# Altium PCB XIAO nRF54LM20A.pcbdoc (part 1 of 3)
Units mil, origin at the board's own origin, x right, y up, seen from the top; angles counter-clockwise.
Board outline 1393.7 x 1456.69 mil, 6 copper layers (Top Layer, L2.Cu, L3.Cu, L4.Cu, L5.Cu, Bottom Layer), stack 1.58 mil thick; 146 components, 0 nets, 519 pads, 402 vias.
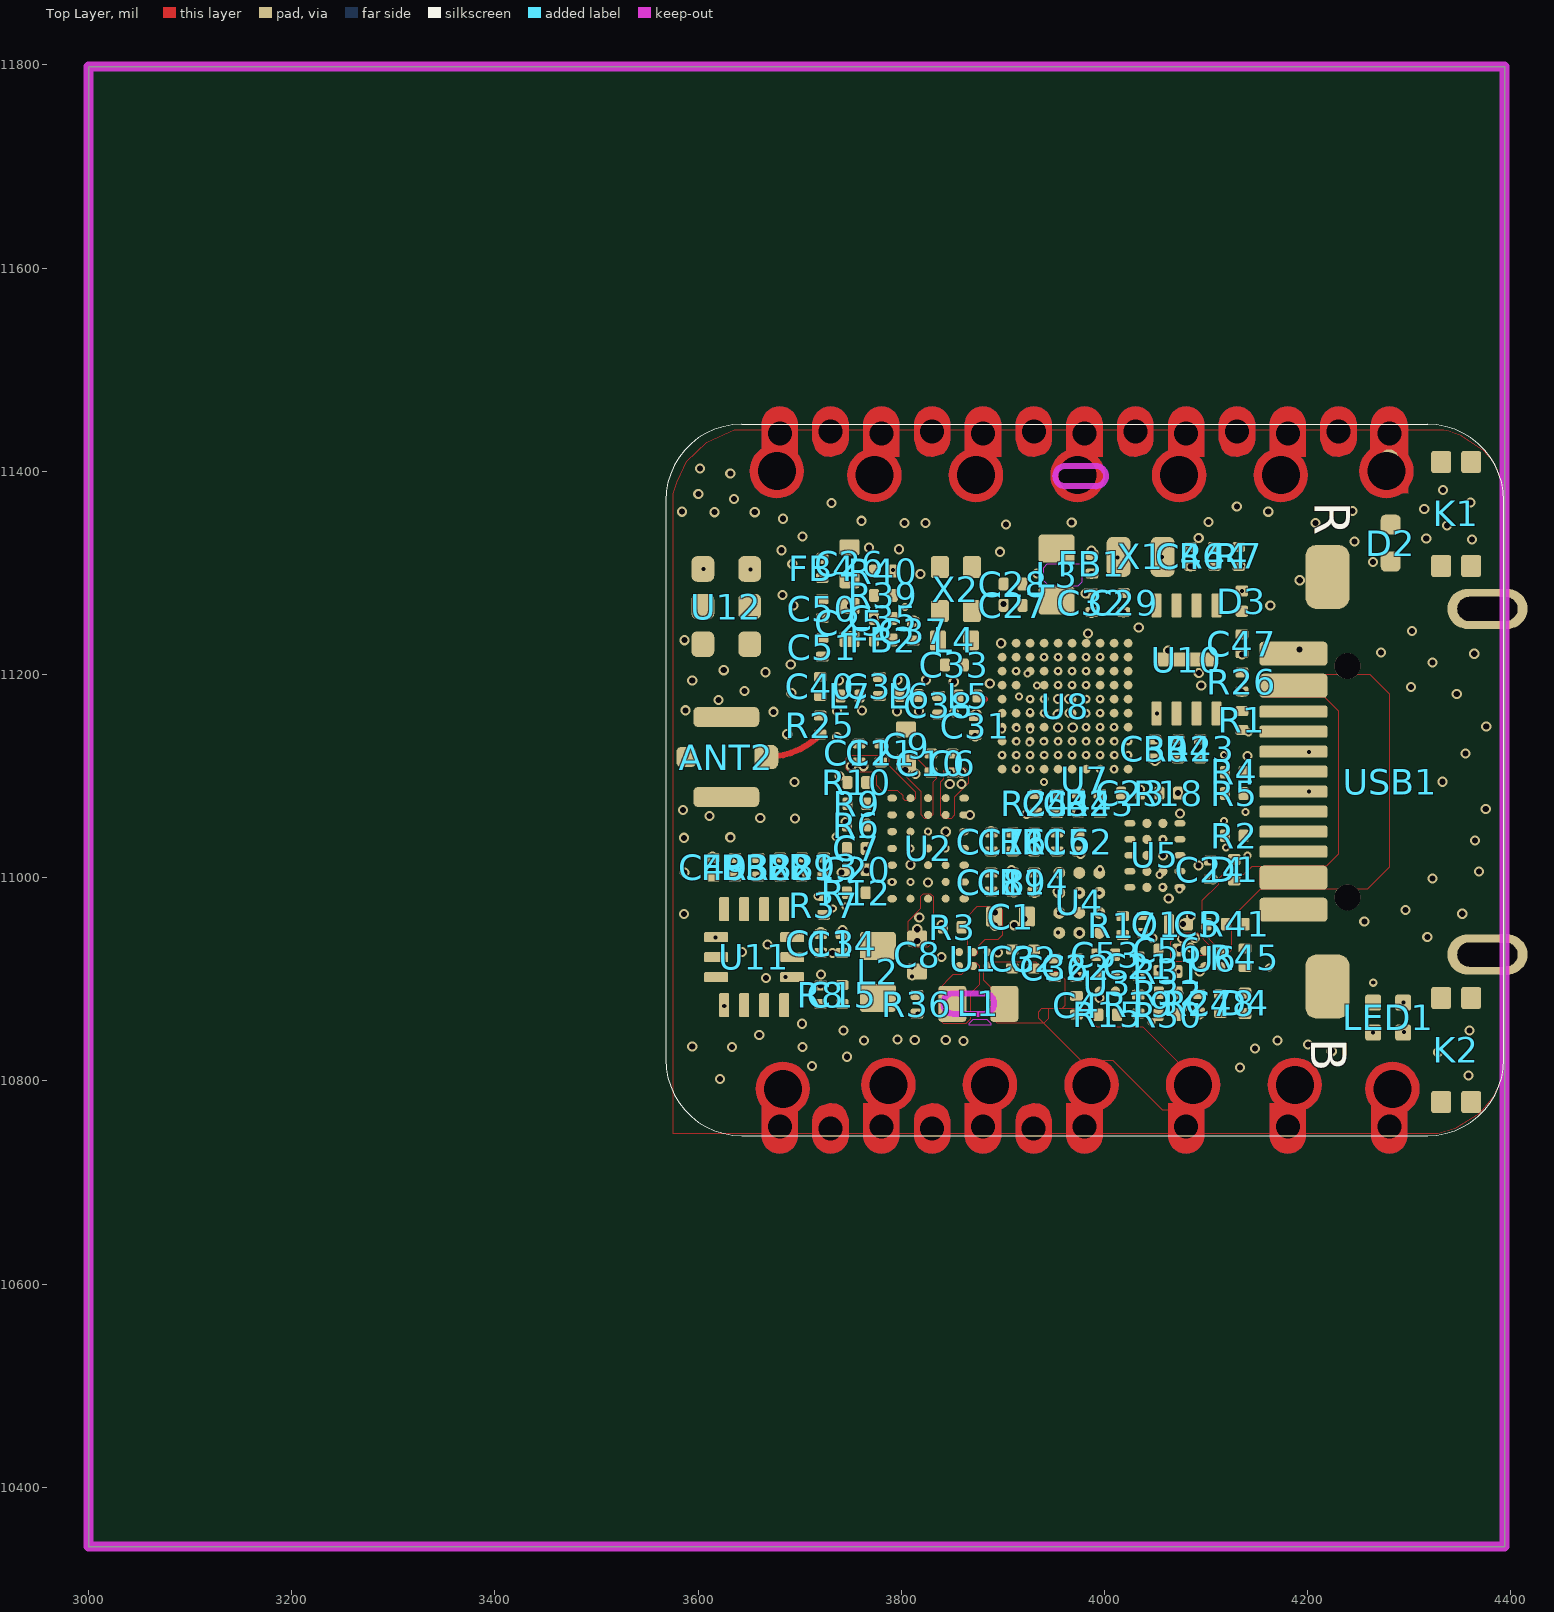
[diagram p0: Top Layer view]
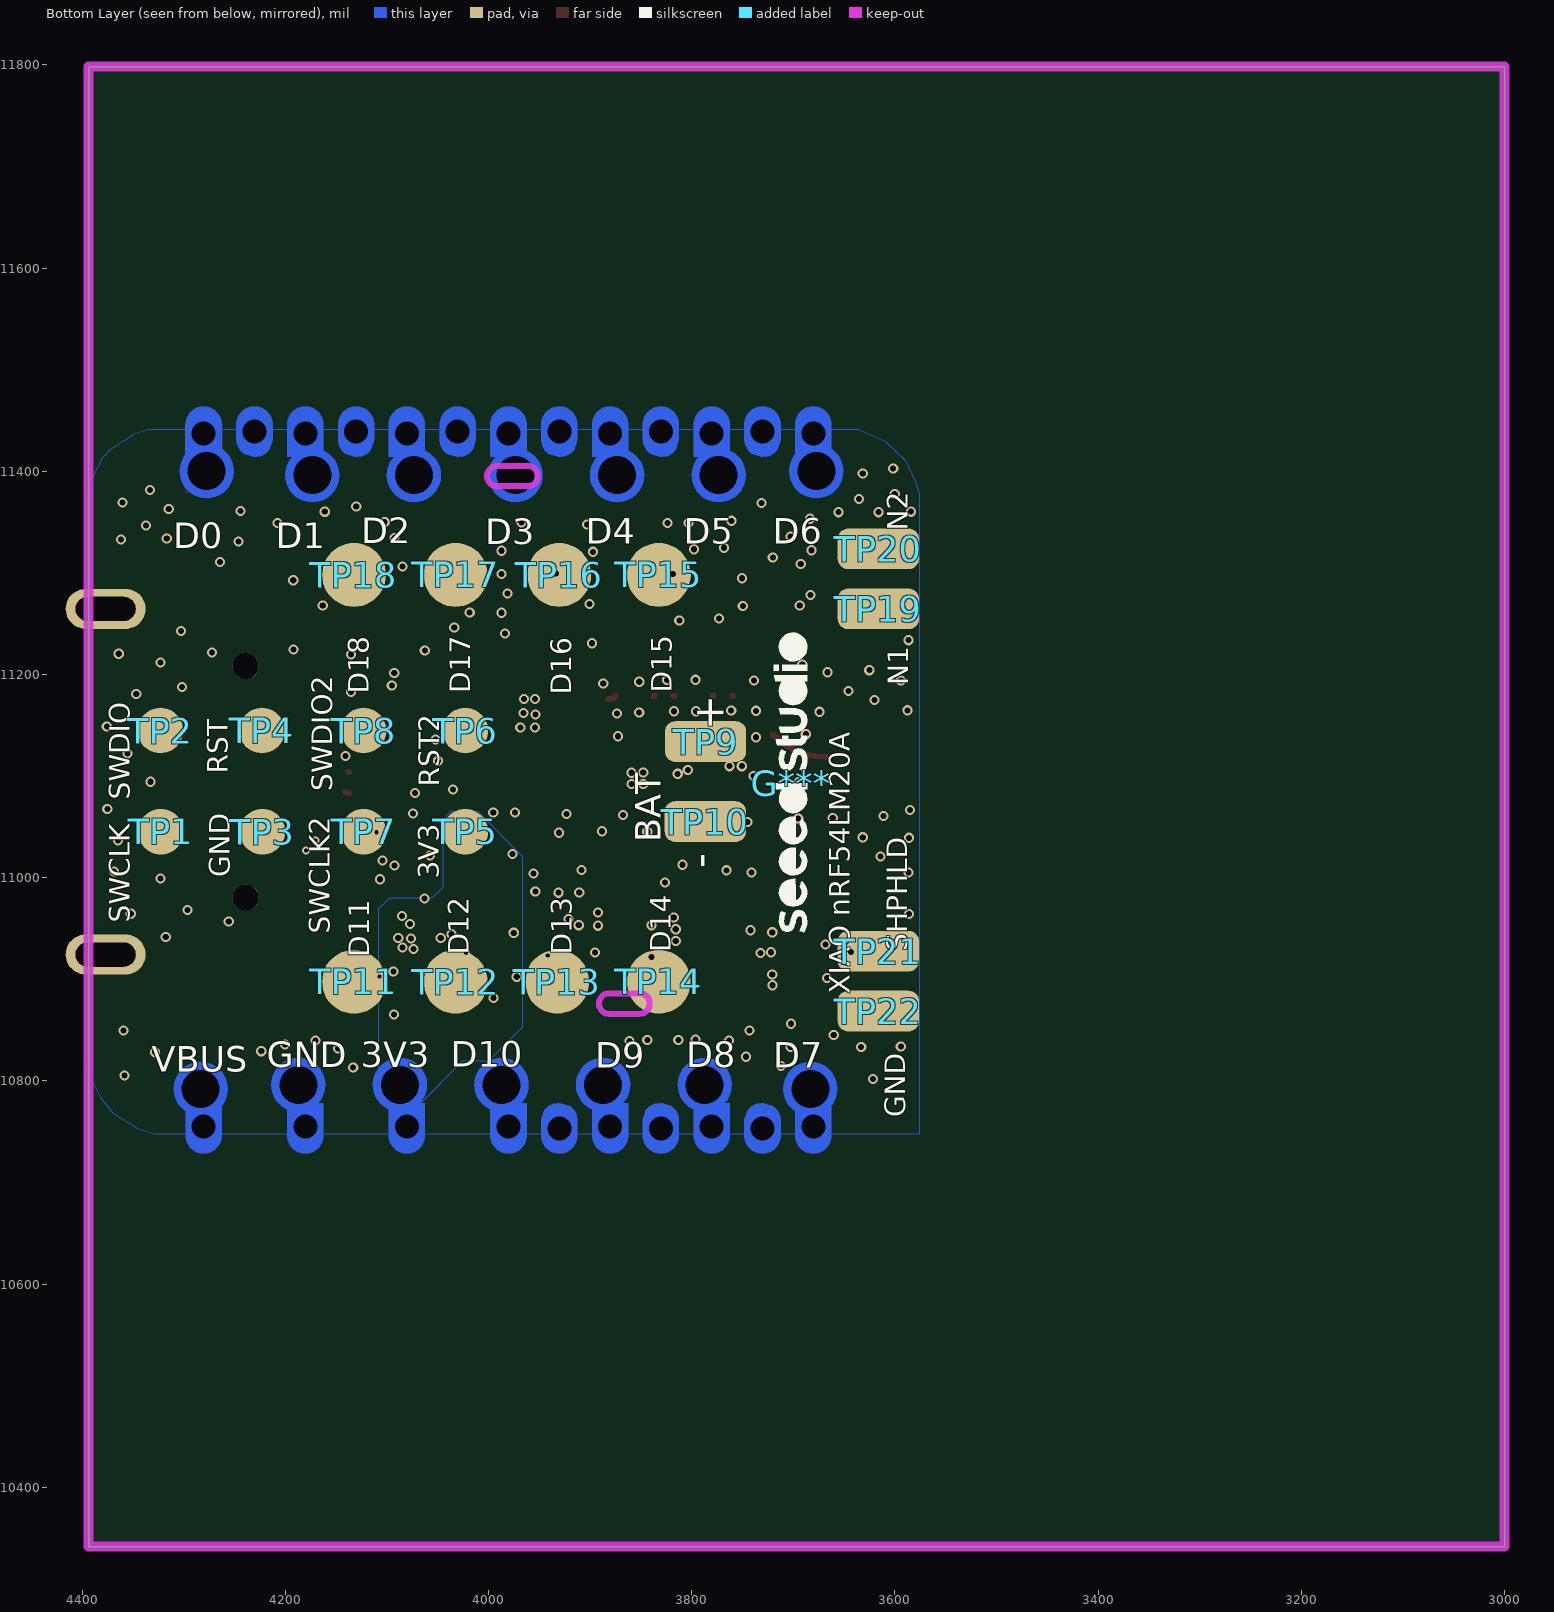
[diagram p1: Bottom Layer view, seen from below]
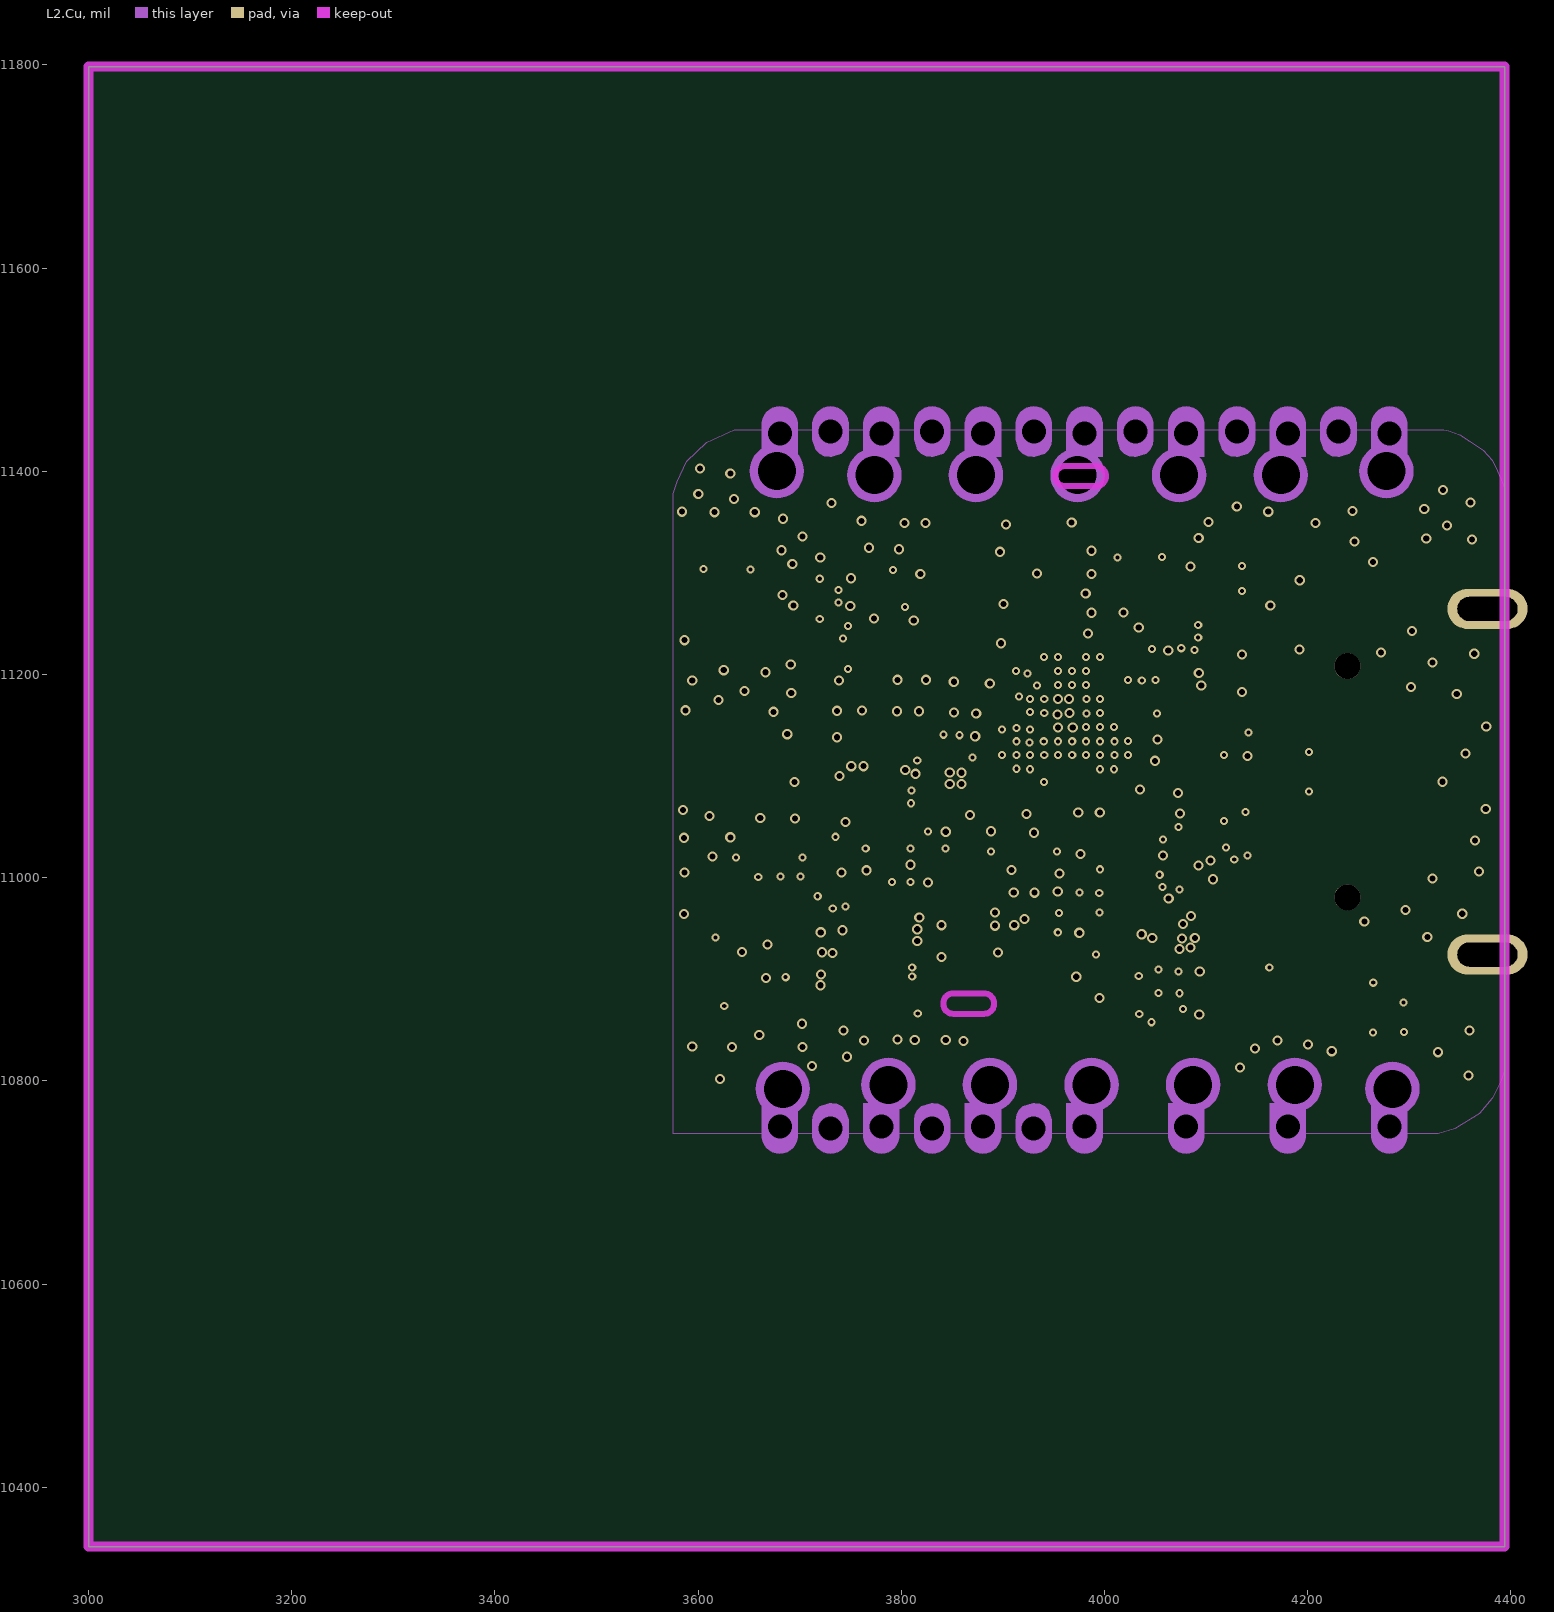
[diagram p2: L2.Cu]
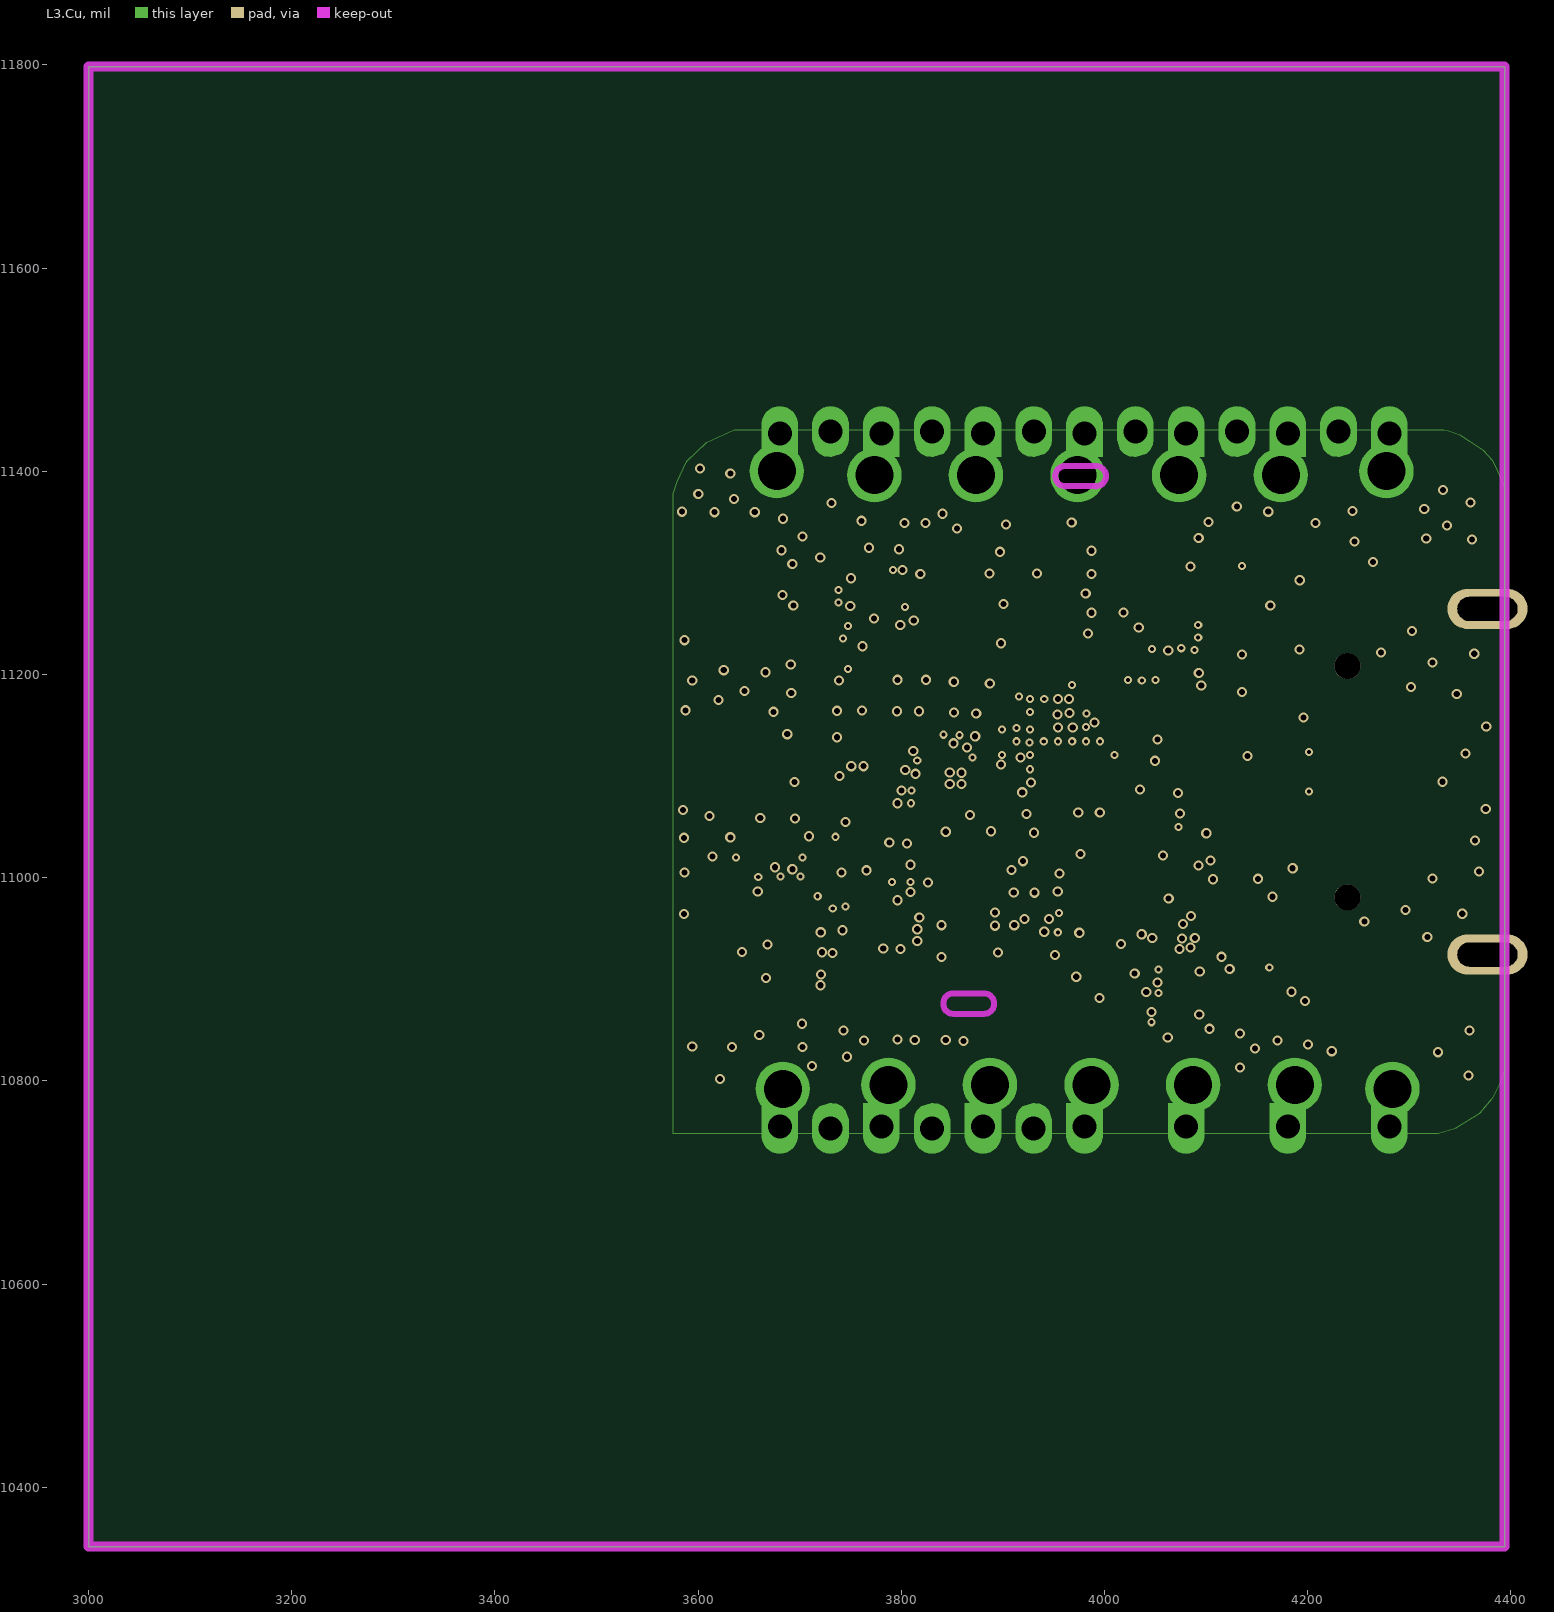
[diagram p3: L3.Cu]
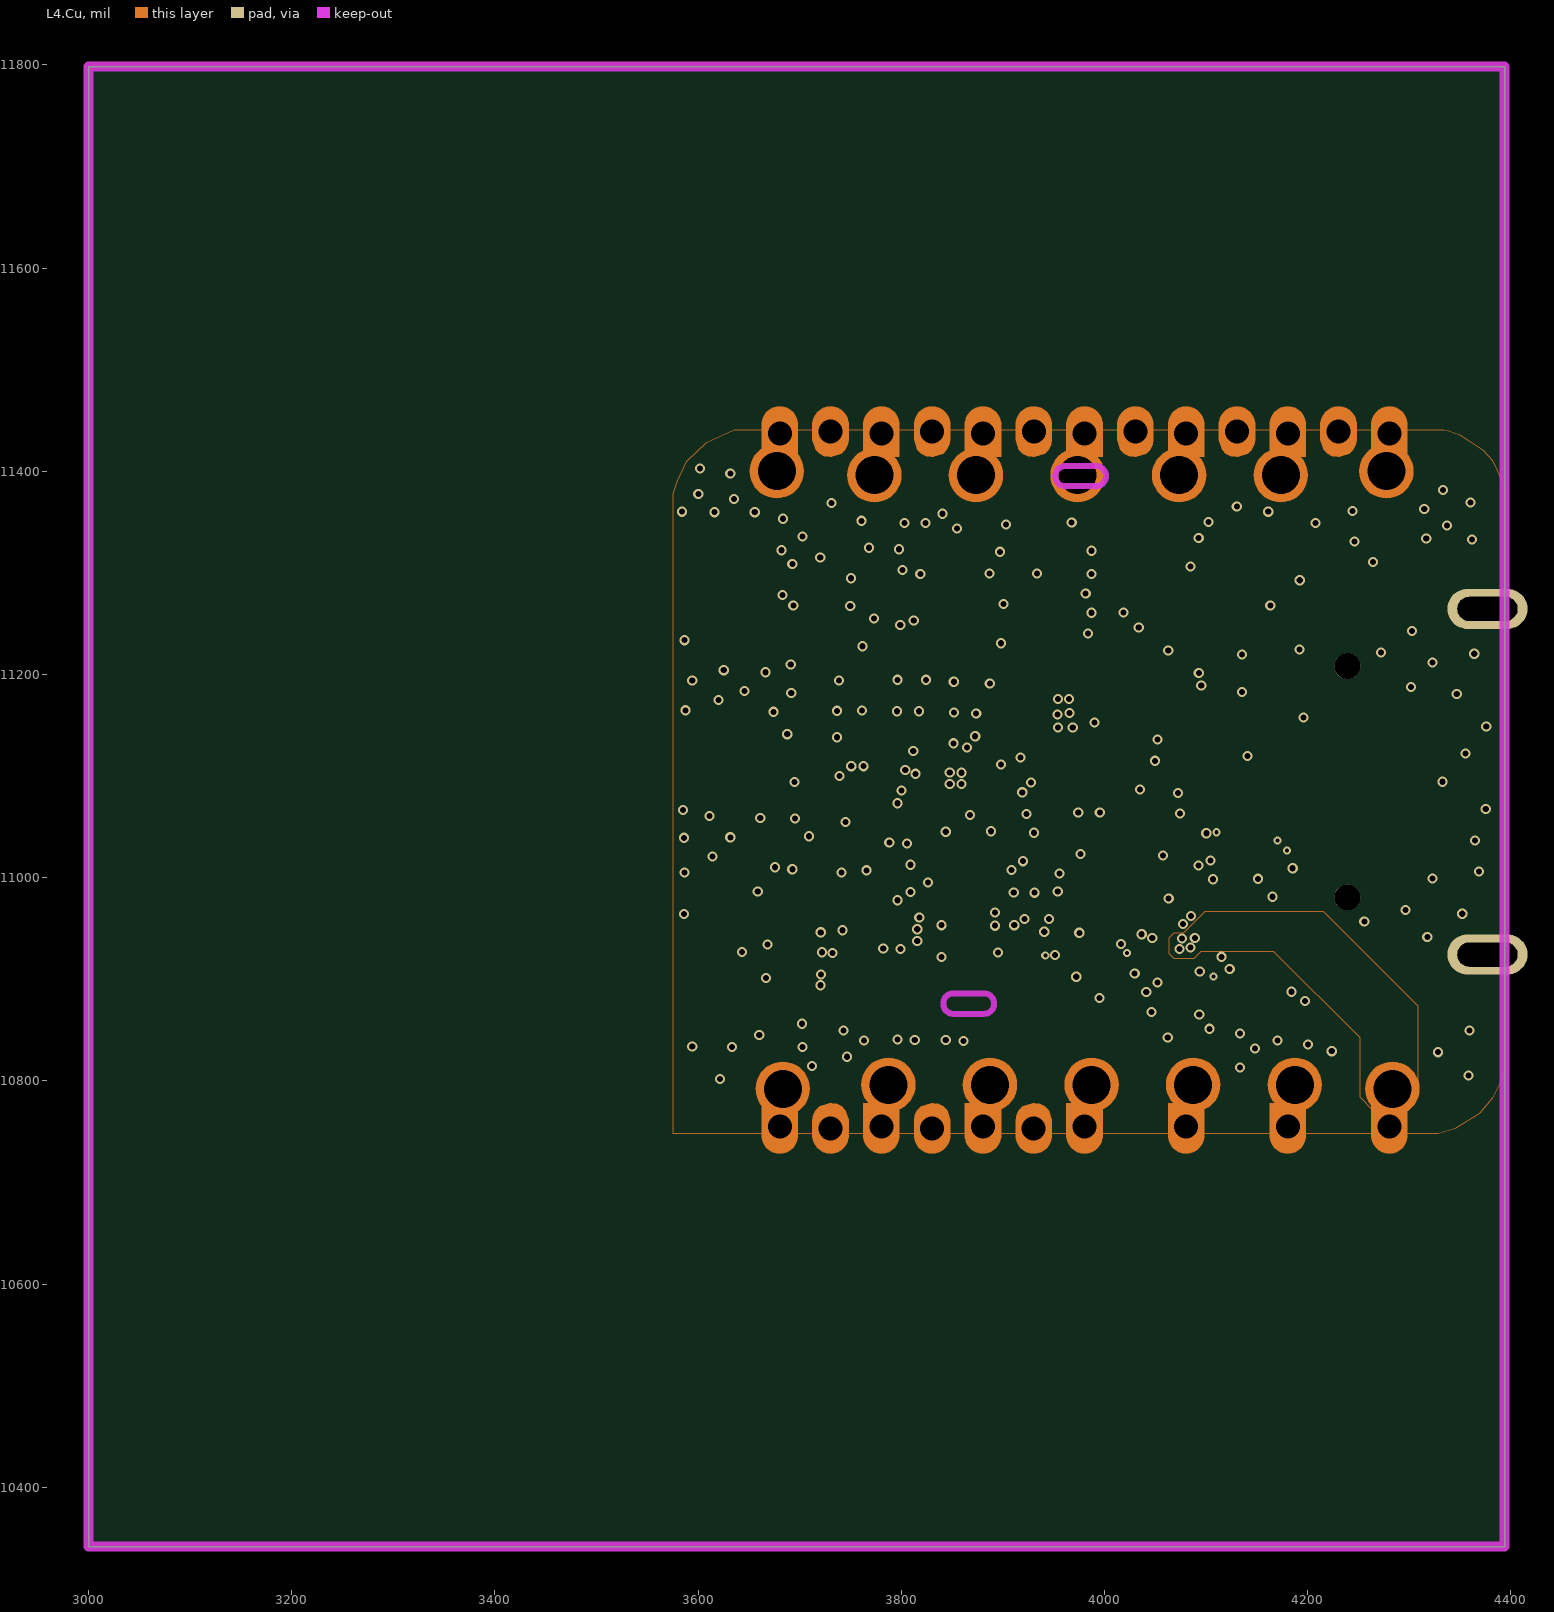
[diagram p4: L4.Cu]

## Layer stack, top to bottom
Top Solder Mask Layer: solder mask 0.01, Dk 0
Top Layer: signal copper 0.035
dielectric 1: surface 0.1, FR4, Dk 4.5
L2.Cu: signal copper 0.035
dielectric 2: surface 0.535, FR4, Dk 4.5
L3.Cu: signal copper 0.035
dielectric 3: surface 0.1, FR4, Dk 4.5
L4.Cu: signal copper 0.035
dielectric 4: surface 0.535, FR4, Dk 4.5
L5.Cu: signal copper 0.035
dielectric 5: surface 0.1, FR4, Dk 4.5
Bottom Layer: signal copper 0.035
Bottom Solder Mask Layer: solder mask 0.01, Dk 0

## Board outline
3000,11798.35 3000,10341.66 4393.7,10341.66 4393.7,11798.35

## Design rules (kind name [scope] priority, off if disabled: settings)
BoardOutlineClearance copperThickness1oz [All] p0: genericclearance=10 ignorepadtopadclearanceinfootprint=FALSE except(0: Arc-SplitContinuation Track-SplitContinuation SMDPad-SplitContinuation THPad-SplitContinuation Via-SplitContinuation Fill-SplitContinuation Poly-SplitContinuation Region-SplitContinuation Text-SplitContinuation)
BoardOutlineClearance otherClearance [All] p0: genericclearance=10 ignorepadtopadclearanceinfootprint=FALSE except(0: Arc-SplitContinuation Track-SplitContinuation SMDPad-SplitContinuation THPad-SplitContinuation Via-SplitContinuation Fill-SplitContinuation Poly-SplitContinuation Region-SplitContinuation Text-SplitContinuation)
Clearance copperThickness1oz [All] p1: gap=7 ignorepadtopadclearanceinfootprint=FALSE
Clearance otherClearance [All] p1: gap=7 ignorepadtopadclearanceinfootprint=FALSE
DiffPairsRouting differentialPair [All] p1: maxuncoupledlength=10 minlimit=5 maxlimit=Infinity mostfreqgap=6 toplayer_minwidth=5 toplayer_prefwidth=100 toplayer_maxwidth=100 bottomlayer_minwidth=5 bottomlayer_prefwidth=100 bottomlayer_maxwidth=100 midlayer1_minwidth=5 midlayer1_prefwidth=100 midlayer1_maxwidth=100 midlayer2_minwidth=5 midlayer2_prefwidth=100 midlayer2_maxwidth=100 midlayer3_minwidth=5 midlayer3_prefwidth=100 midlayer3_maxwidth=100 midlayer4_minwidth=5 midlayer4_prefwidth=100 midlayer4_maxwidth=100
PasteMaskExpansion pad_to_mask_clearance [All] p1: expansion=0
PlaneConnect innerPlane [All] p1: planeconnectstyle=Relief reliefexpansion=20 reliefentries=4 reliefconductorwidth=10 reliefairgap=10
PolygonConnect copper0 [All] p1: connectstyle=Direct reliefentries=4 reliefconductorwidth=10 polygonreliefangle="90 Angle" airgapwidth=10
PolygonConnect copper1 [All] p1: connectstyle=Relief reliefentries=4 reliefconductorwidth=19.68503937007874 polygonreliefangle="90 Angle" airgapwidth=19.68503937007874
RoutingVias viaSize [All] p1: viastyle="Through Hole" holewidth=24 minholewidth=19.7 maxholewidth=393.7 width=24 minwidth=19.7 maxwidth=393.7
SolderMaskExpansion pad_to_mask_clearance [IsVia] p1: useseparateexpansions=TRUE expansion=-1000 expansionbottom=-1000
SolderMaskExpansion pad_to_mask_clearance [All] p2: useseparateexpansions=TRUE expansion=0 expansionbottom=0
Width copperThickness1oz [All] p1: maxlimit=100 minlimit=5 preferedwidth=10

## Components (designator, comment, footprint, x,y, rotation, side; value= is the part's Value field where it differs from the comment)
ANT2 "ECT818000500" Connector:IPEX-GEN4-SMD-1.7X1.7X1.0MM 3627.7,11118.7 r180 top
C1 "10uF" Capacitor:C0402 3907.47,10961.62 r0 top
C2 "4.7uF" Capacitor:C0201 3930.34,10919.9 r90 top
C3 "4.7uF" Capacitor:C0201 3909.26,10919.98 r90 top
C4 "100nF" Capacitor:C0201 3972.3,10874.42 r90 top
C5 "100nF" Capacitor:C0201 4091.2,10954.2 r180 top
C6 "1uF" Capacitor:C0201 3850.2,11112.7 r90 top
C7 "100nF" Capacitor:C0201 3755.7,11028.7 r180 top
C8 "10uF" Capacitor:C0402 3815.62,10923.86 r270 top
C9 "10uF" Capacitor:C0402 3804.7,11129.7 r90 top
C10 "100nF" Capacitor:C0201 3829.2,11112.81 r90 top
C11 "2.2uF" Capacitor:C0201 3779.84,11122.78 r90 top
C12 "100nF" Capacitor:C0201 3758.34,11122.78 r90 top
C13 "4.7uF" Capacitor:C0201 3720.7,10935.26 r90 top
C14 "4.7uF" Capacitor:C0201 3741.7,10935.14 r90 top
C15 "100nF" Capacitor:C0201 3741.82,10884.94 r270 top
C16 "100nF" Capacitor:C0201 3909.62,11035.18 r90 top
C17 "1uF" Capacitor:C0201 3888.62,11035.18 r90 top
C18 "4.7uF" Capacitor:C0201 3888.38,10995.66 r270 top
C19 "100nF" Capacitor:C0201 3909.38,10995.66 r270 top
C20 "100nF" Capacitor:C0201 3755.7,11007.7 r180 top
C21 "100nF" Capacitor:C0201 4033.22,10912.99 r90 top
C22 "100nF" Capacitor:C0201 3972.2,10911.7 r270 top
C23 "100nF" Capacitor:C0201 4025.7,11083.2 r180 top
C24 "100nF" Capacitor:C0201 4104.2,11007.7 r90 top
C25 "300pF" Capacitor:C0402 3749.06,11250.94 r270 top
C26 "300pF" Capacitor:C0402 3749.06,11308.94 r90 top
C27 "4.7uF" Capacitor:C0201 3910.04,11267.98 r180 top
C28 "4.7uF" Capacitor:C0201 3910.04,11288.98 r180 top
C29 "100nF" Capacitor:C0201 4018.7,11270.7 r90 top
C30 "100nF" Capacitor:C0201 4049.2,11126.7 r270 top
C31 "100nF" Capacitor:C0201 3872.7,11149.7 r90 top
C32 "2.2uF" Capacitor:C0201 3987.49,11270.48 r90 top
C33 "1pF" Capacitor:C0201 3852.2,11209.32 r180 top
C34 "4.7uF" Capacitor:C0201 3974.1,11073.34 r270 top
C35 "2.2uF" Capacitor:C0201 3782.36,11255.17 r0 top
C36 "4.7uF" Capacitor:C0201 3951,10911.3 r90 top
C37 "2.2uF" Capacitor:C0201 3811.7,11242.45 r90 top
C38 "1.2pF" Capacitor:C0201 3836.7,11169.7 r270 top
C39 "1.2pF" Capacitor:C0201 3778.46,11188.14 r90 top
C40 "1.2pF" Capacitor:C0201 3720.2,11188.2 r90 top
C46 "100nF" Capacitor:C0201 4084.7,11316.2 r90 top
C47 "100nF" Capacitor:C0201 4135.2,11230.2 r90 top
C48 "100nF" Capacitor:C0201 4114.2,10876.2 r270 top
C49 "100nF" Capacitor:C0201 3615.2,11010.26 r90 top
C50 "4.7uF" Capacitor:C0201 3722.2,11264.7 r90 top
C51 "100nF" Capacitor:C0201 3722.2,11226.7 r270 top
C52 "100nF" Capacitor:C0201 3974.2,11035.2 r90 top
C53 "100nF" Capacitor:C0201 4001.2,10924.2 r0 top
C54 "2.2uF" Capacitor:C0201 3953.23,11073.05 r270 top
C56 "100nF" Capacitor:C0201 4062.45,10928.7 r180 top
D1 "DF2B7ASL,L3F" Diode:ESD-0201 4127.7,11007.7 r270 top
D2 "Red" Diode:LED-0402 4281.7,11329.2 r90 top
D3 "DF2B7ASL,L3F" Diode:ESD-0201 4135.2,11272.2 r270 top
D4 "DF2B7ASL,L3F" Diode:ESD-0201 4138.2,10876.2 r90 top
FB1 "120R" Inductor:L0201 3987.54,11308.48 r90 top
FB2 "120R" Inductor:L0201 3782.2,11233.95 r180 top
FB3 "120R" Inductor:L0201 3636.19,11010.21 r90 top
FB4 "120R" Inductor:L0201 3722.2,11304.2 r90 top
G*** "LOGO" Logo:LOGO-SEEED-NEW-0.83X7.5MM 3701.88,11092.74 r90 bottom
K1 "TS-1001S" Switch:SW4-SMD-2.8-2.6X1.6X0.53MM 4346.15,11357.96 r90 top
K2 "TS-1001S" Switch:SW4-SMD-2.8-2.6X1.6X0.53MM 4346.15,10830.41 r270 top
L1 "1uH" Inductor:L0603 3875.82,10875.78 r0 top
L2 "2.2uH" Inductor:L0603 3776.9,10907.18 r270 top
L3 "4.7uH" Inductor:L0603 3952.84,11298.24 r270 top
L4 "1nH" Inductor:L0402 3852.2,11233.45 r0 top
L5 "3.6nH" Inductor:L0201 3865.7,11178.7 r180 top
L6 "4.7nH" Inductor:L0201 3807.7,11179.2 r180 top
L7 "2.2nH" Inductor:L0201 3749.45,11178.7 r180 top
LED1 "FC-B1010RGBT-HG" Diode:RGB4P-0.65-1X1X0.85MM 4279.2,10862.2 r270 top
Q1 "LN237N3T5G" Mosfet:PMOS_1.0X0.6X0.35MM 4050.7,10954.2 r270 top
R1 "5.1K" Resistor:R0201 4135.2,11154.7 r270 top
R2 "5.1K" Resistor:R0201 4127.7,11041.2 r0 top
R3 "249K" Resistor:R0201 3850.2,10951.2 r0 top
R4 "22R" Resistor:R0201 4127.7,11103.7 r180 top
R5 "22R" Resistor:R0201 4127.7,11082.7 r180 top
R6 "10K" Resistor:R0201 3755.84,11051.7 r0 top
R7 "10K" Resistor:R0201 4132.2,11316.2 r90 top
R8 "0R" Resistor:R0201 3720.58,10884.82 r90 top
R9 "0R" Resistor:R0201 3756.2,11072.7 r0 top
R10 "470K" Resistor:R0201 3756.2,11093.7 r0 top
R11 "0R" Resistor:R0201 3930.62,11035.18 r90 top
R12 "4.7K" Resistor:R0201 3755.7,10985.2 r180 top
R13 "4.7K" Resistor:R0201 3723.7,11010.7 r270 top
R14 "0R" Resistor:R0201 3930.62,10995.68 r270 top
R15 "100K" Resistor:R0201 4003.1,10864.98 r0 top
R16 "10K" Resistor:R0201 3953.2,11035.2 r90 top
R17 "100K" Resistor:R0201 4017.91,10952.83 r90 top
R18 "100K" Resistor:R0201 4063.2,11083.2 r0 top
R19 "100K" Resistor:R0201 4033.22,10875.49 r270 top
R23 "0R" Resistor:R0201 3995.36,11073.2 r270 top
R24 "200R" Resistor:R0201 3932.2,11073.2 r90 top
R25 "0R" Resistor:R0201 3720.2,11150.2 r270 top
R26 "100K" Resistor:R0201 4135.2,11192.7 r270 top
R27 "100K" Resistor:R0201 4092.7,10876.45 r270 top
R28 "4.7K" Resistor:R0201 3680.62,11010.44 r90 top
R29 "4.7K" Resistor:R0201 3702.06,11010.46 r90 top
R30 "2K" Resistor:R0201 4062.45,10865.2 r180 top
R31 "2K" Resistor:R0201 4062.45,10907.7 r180 top
R32 "2K" Resistor:R0201 4062.7,10886.7 r180 top
R36 "1M" Resistor:R0201 3815.34,10875.38 r270 top
R37 "100K" Resistor:R0201 3723.7,10972.7 r90 top
R38 "100K" Resistor:R0201 3658.98,11010.2 r90 top
R39 "0R" Resistor:R0201 3782.36,11277.75 r180 top
R40 "0R" Resistor:R0201 3782.36,11301.67 r180 top
R41 "100K" Resistor:R0201 4128.7,10954.2 r180 top
R42 "100K" Resistor:R0201 4072.7,11126.7 r270 top
R43 "100K" Resistor:R0201 4094.2,11126.7 r270 top
R44 "100K" Resistor:R0201 4108.2,11316.2 r90 top
R45 "100K" Resistor:R0201 4138.2,10921.2 r270 top
TP1 "Test Point" Misc:TP-D45MIL 4322.57,11045.2 r180 bottom
TP2 "Test Point" Misc:TP-D45MIL 4322.97,11144.81 r180 bottom
TP3 "Test Point" Misc:TP-D45MIL 4222.57,11045.2 r180 bottom
TP4 "Test Point" Misc:TP-D45MIL 4222.97,11144.81 r180 bottom
TP5 "Test Point" Misc:TP-D45MIL 4022.97,11045.2 r180 bottom
TP6 "Test Point" Misc:TP-D45MIL 4022.97,11144.81 r180 bottom
TP7 "Test Point" Misc:TP-D45MIL 4122.97,11045.2 r180 bottom
TP8 "Test Point" Misc:TP-D45MIL 4122.97,11144.81 r180 bottom
TP9 "Test Point" Misc:TP-80X40MIL 3786.35,11133.98 r0 bottom
TP10 "Test Point" Misc:TP-80X40MIL 3786.55,11055.24 r0 bottom
TP11 "Test Point" Misc:TP-1.6MM-ROUND 4132.41,10897.56 r0 bottom
TP12 "Test Point" Misc:TP-1.6MM-ROUND 4032.41,10897.56 r0 bottom
TP13 "Test Point" Misc:TP-1.6MM-ROUND 3932.41,10897.56 r0 bottom
TP14 "Test Point" Misc:TP-1.6MM-ROUND 3832.48,10897.56 r0 bottom
TP15 "Test Point" Misc:TP-1.6MM-ROUND 3832.41,11297.96 r0 bottom
TP16 "Test Point" Misc:TP-1.6MM-ROUND 3930.45,11297.96 r0 bottom
TP17 "Test Point" Misc:TP-1.6MM-ROUND 4032.41,11297.96 r0 bottom
TP18 "Test Point" Misc:TP-1.6MM-ROUND 4132.41,11297.96 r0 bottom
TP19 "Test Point" Misc:TP-80X40MIL 3616.27,11264.49 r0 bottom
TP20 "Test Point" Misc:TP-80X40MIL 3616.27,11323.63 r0 bottom
TP21 "Test Point" Misc:TP-80X40MIL 3616.27,10927.6 r0 bottom
TP22 "Test Point" Misc:TP-80X40MIL 3616.27,10868.73 r0 bottom
U1 "TPS628438YKAR" Ic:BGA6-0.35-0.85X1.2X0.4MM 3870.7,10919.87 r270 top
U2 "nPM1300-CAAA" Ic:WLCSP35-0.44-3.0775X2.3775X0.512MM 3826.34,11028.77 r270 top
U3 "TPS22916CNYFPR" Ic:WLCSP4-0.4-0.77X0.77X0.33MM 4002.86,10896.01 r0 top
U4 "英联" Ic:csp12-1.9x1.4MM 3994.82,11004.7 r270 top
U5 "ATSAMD11D14A-UUT" Ic:WLCSP20-0.4-2.4X1.9X0.5MM_SMALL 4049.58,11021.95 r180 top
U6 "TPS22916CNYFPR" Ic:WLCSP4-0.4-0.77X0.77X0.33MM 4106.7,10920.2 r0 top
U7 "XIAO-Add-On-Plus" Seeed_Studio_XIAO_Series:XIAO-Add-On-PRO 3980.36,11096.15 r0 top
U8 "nRF54LM20A" Ic:CSP98_0.35_3.67x3.85x0.61mm 3961.21,11172.36 r0 top
U10 "PY25Q64HA-UXH-IR" Ic:USON8-0.5-3X2MM 4080.7,11214.7 r90 top
U11 "LSM6DS3TR-C" Ic:LGA14-0.5-2.5X3X0.86MM 3655.2,10921.7 r270 top
U12 "MSM261DGT006" Misc:MIC6P-0.94-4X2X1.1MM 3627.7,11266.7 r0 top
USB1 "USB2.0 Type C" Connector:USB2.0-TYPE-C_USB-31C-F-16P 4189.9,11094.41 r180 top
X1 "32.768KHZ-7PF-20ppm" Crystal:X2-SMD-1.6X1.0MM 4035.54,11315.7 r0 top
X2 "32MHz-8pF-10ppm-70R" Crystal:X4-SMD-1.6X1.2MM 3853.7,11283.95 r270 top

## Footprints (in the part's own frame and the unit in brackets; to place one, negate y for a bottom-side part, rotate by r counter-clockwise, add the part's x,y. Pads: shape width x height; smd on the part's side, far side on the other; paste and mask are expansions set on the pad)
Capacitor:C0201 [mm]
  rrect40% 0.25x0.32 smd: 1(-0.235,0) 2(0.235,0)
Capacitor:C0402 [mm]
  rrect26% 0.4x0.5 smd: 1(-0.413,0) 2(0.413,0)
Connector:IPEX-GEN4-SMD-1.7X1.7X1.0MM [mm]
  rrect50% 0.6x0.6 smd: 1(-1,0)
  rrect50% 1.65x0.5 smd: 2(0,1) 3(0,-1)
  rrect50% 0.5x0.5 smd: 4(1,0)
Connector:USB2.0-TYPE-C_USB-31C-F-16P [mm]
  rrect30% 1.7x0.6 smd: A1B12(0.1,3.2) A4B9(0.1,2.4) B1A12(0.1,-3.2) B4A9(0.1,-2.4)
  rrect30% 1.7x0.3 smd: A5(0.1,1.25) A6(0.1,0.25) A7(0.1,-0.25) A8(0.1,-1.25) B5(0.1,-1.75) B6(0.1,-0.75) B7(0.1,0.75) B8(0.1,1.75)
  oval 2x1 hole 0.6 slot 1.5 at 0 deg paste+0 mask+0.051: S1(-4.75,4.32) S2(-4.75,-4.32)
  rrect50% 1.1x1.6 smd: S3(-0.75,5.12) S4(-0.75,-5.12)
  round 0.65 hole 0.65 unplated paste+0 mask+0.051: ""(-1.25,2.89) ""(-1.25,-2.89)
Crystal:X2-SMD-1.6X1.0MM [mm]
  rrect50% 0.6x1 smd: 1(-0.55,0) 2(0.55,0)
Crystal:X4-SMD-1.6X1.2MM [mm]
  rrect30% 0.55x0.45 smd: 1(-0.55,-0.4) 2(0.55,-0.4) 3(0.55,0.4) 4(-0.55,0.4)
Diode:ESD-0201 [mil]
  rrect40% 11x12.5 smd: 1(-10.03,0) 2(10.03,0)
Diode:LED-0402 [mm]
  rrect50% 0.5x0.5 smd paste+0 mask+0.051: 1(0.462,0) 2(-0.463,0)
Diode:RGB4P-0.65-1X1X0.85MM [mm]
  rrect30% 0.4x0.4 smd: 1(0.375,0.375) 2(0.375,-0.375) 3(-0.375,-0.375) 4(-0.375,0.375)
Ic:BGA6-0.35-0.85X1.2X0.4MM [mm]
  rrect100% 0.2x0.2 smd paste+0 mask+0.032: A1(-0.175,0.35) A2(0.175,0.35) B1(-0.175,0) B2(0.175,0) C1(-0.175,-0.35) C2(0.175,-0.35)
Ic:csp12-1.9x1.4MM [mm]
  round 0.3 smd: A1(0,0) A2(0,-0.5) A3(0,-1) B1(0.5,0) B2(0.5,-0.5) B3(0.5,-1) C1(1,0) C2(1,-0.5) C3(1,-1) D1(1.5,0) D2(1.5,-0.5) D3(1.5,-1)
Ic:CSP98_0.35_3.67x3.85x0.61mm [mm]
  round 0.22 smd: A1(-1.575,1.485) A2(-1.225,1.485) A3(-0.875,1.485) A4(-0.525,1.485) A5(-0.175,1.485) A6(0.175,1.485) A7(0.525,1.485) A8(0.875,1.485) A9(1.225,1.485) A10(1.575,1.485) B1(-1.575,1.135) B2(-1.225,1.135) B3(-0.875,1.135) B4(-0.525,1.135) B5(-0.175,1.135) B6(0.175,1.135) B7(0.525,1.135) B8(0.875,1.135) B9(1.225,1.135) B10(1.575,1.135) C1(-1.575,0.785) C2(-1.225,0.785) C3(-0.875,0.785) C4(-0.525,0.785) C5(-0.175,0.785) C6(0.175,0.785) C7(0.525,0.785) C8(0.875,0.785) C9(1.225,0.785) C10(1.575,0.785) D1(-1.575,0.435) D2(-1.225,0.435) D4(-0.525,0.435) D5(-0.175,0.435) D6(0.175,0.435) D7(0.525,0.435) D8(0.875,0.435) D9(1.225,0.435) D10(1.575,0.435) E1(-1.575,0.085) E3(-0.875,0.085) E4(-0.525,0.085) E5(-0.175,0.085) E6(0.175,0.085) E7(0.525,0.085) E8(0.875,0.085) E9(1.225,0.085) E10(1.575,0.085) F1(-1.575,-0.265) F2(-1.225,-0.265) F3(-0.875,-0.265) F4(-0.525,-0.265) F5(-0.175,-0.265) F6(0.175,-0.265) F7(0.525,-0.265) F8(0.875,-0.265) F9(1.225,-0.265) F10(1.575,-0.265) G1(-1.575,-0.615) G2(-1.225,-0.615) G3(-0.875,-0.615) G4(-0.525,-0.615) G5(-0.175,-0.615) G6(0.175,-0.615) G7(0.525,-0.615) G8(0.875,-0.615) G9(1.225,-0.615) G10(1.575,-0.615) H1(-1.575,-0.965) H2(-1.225,-0.965) H3(-0.875,-0.965) H4(-0.525,-0.965) H5(-0.175,-0.965) H6(0.175,-0.965) H7(0.525,-0.965) H8(0.875,-0.965) H9(1.225,-0.965) H10(1.575,-0.965) J1(-1.575,-1.315) J2(-1.225,-1.315) J3(-0.875,-1.315) J4(-0.525,-1.315) J5(-0.175,-1.315) J6(0.175,-1.315) J7(0.525,-1.315) J8(0.875,-1.315) J9(1.225,-1.315) J10(1.575,-1.315) K1(-1.575,-1.665) K2(-1.225,-1.665) K3(-0.875,-1.665) K4(-0.525,-1.665) K5(-0.175,-1.665) K6(0.175,-1.665) K7(0.525,-1.665) K8(0.875,-1.665) K9(1.225,-1.665) K10(1.575,-1.665)
Ic:LGA14-0.5-2.5X3X0.86MM [mm]
  rrect25% 0.6x0.25 smd: 1(-1.2,0.75) 2(-1.2,0.25) 3(-1.2,-0.25) 4(-1.2,-0.75) 8(1.2,-0.75) 9(1.2,-0.25) 10(1.2,0.25) 11(1.2,0.75)
  rrect25% 0.25x0.6 smd: 5(-0.5,-0.95) 6(0,-0.95) 7(0.5,-0.95) 12(0.5,0.95) 13(0,0.95) 14(-0.5,0.95)
Ic:USON8-0.5-3X2MM [mm]
  rrect25% 0.6x0.26 smd: 1(-1.35,0.75) 2(-1.35,0.25) 3(-1.35,-0.25) 4(-1.35,-0.75) 5(1.35,-0.75) 6(1.35,-0.25) 7(1.35,0.25) 8(1.35,0.75)
  rrect25% 0.35x1.6 smd: 9(0,0)
Ic:WLCSP4-0.4-0.77X0.77X0.33MM [mm]
  round 0.24 smd: A1(-0.2,0.2) A2(0.2,0.2) B1(-0.2,-0.2) B2(0.2,-0.2)
Ic:WLCSP20-0.4-2.4X1.9X0.5MM_SMALL [mm]
  oval 0.28x0.16 smd: A1(-0.625,0.8) A4(0.625,0.8) B1(-0.625,0.4) B4(0.625,0.4) C1(-0.625,0) C4(0.625,0) D1(-0.625,-0.4) D4(0.625,-0.4) E1(-0.625,-0.8) E4(0.625,-0.8)
  round 0.23 smd: A2(-0.2,0.8) A3(0.2,0.8) B2(-0.2,0.4) B3(0.2,0.4) C2(-0.2,0) C3(0.2,0) D2(-0.2,-0.4) D3(0.2,-0.4) E2(-0.2,-0.8) E3(0.2,-0.8)
Ic:WLCSP35-0.44-3.0775X2.3775X0.512MM [mm]
  oval 0.18x0.24 smd: A1(-1.257,0.9) A2(-0.838,0.9) A3(-0.419,0.9) A4(0,0.9) A5(0.419,0.9) A6(0.838,0.9) A7(1.257,0.9) E1(-1.257,-0.9) E2(-0.838,-0.9) E3(-0.419,-0.9) E4(0,-0.9) E5(0.419,-0.9) E6(0.838,-0.9) E7(1.257,-0.9)
  round 0.2 smd: B1(-1.257,0.44) B2(-0.838,0.44) B3(-0.419,0.44) B4(0,0.44) B5(0.419,0.44) B6(0.838,0.44) B7(1.257,0.44) C1(-1.257,0) C2(-0.838,0) C3(-0.419,0) C4(0,0) C5(0.419,0) C6(0.838,0) C7(1.257,0) D1(-1.257,-0.44) D2(-0.838,-0.44) D3(-0.419,-0.44) D4(0,-0.44) D5(0.419,-0.44) D6(0.838,-0.44) D7(1.257,-0.44)
Inductor:L0201 [mm]
  rrect40% 0.25x0.32 smd: 1(-0.235,0) 2(0.235,0)
Inductor:L0402 [mm]
  rrect26% 0.4x0.5 smd: 1(-0.413,0) 2(0.413,0)
Inductor:L0603 [mm]
  rrect22% 0.7x0.9 smd: 1(-0.65,0) 2(0.65,0)
Logo:LOGO-SEEED-NEW-0.83X7.5MM [mil]
  silkscreen extent -147,-16 149,17
Misc:MIC6P-0.94-4X2X1.1MM [mm]
  rrect50% 0.57x0.64 smd: 1(0.585,-0.937) 2(0.585,0.003) 3(0.585,0.943) 4(-0.585,0.943) 5(-0.585,0.003) 6(-0.585,-0.937)
Misc:TP-1.6MM-ROUND [mm]
  round 1.6 smd: 1(0,0)
Misc:TP-80X40MIL [mil]
  rrect50% 80x40 smd paste+0 mask+1: 1(0,0)
Misc:TP-D45MIL [mil]
  rrect100% 45x45 smd: 1(0,0)
Mosfet:PMOS_1.0X0.6X0.35MM [mm]
  rrect30% 0.15x0.25 smd: 1(-0.175,-0.325) 2(0.175,-0.325)
  rrect30% 0.5x0.25 smd: 3(0,0.325)
Resistor:R0201 [mm]
  rrect40% 0.25x0.32 smd: 1(-0.235,0) 2(0.235,0)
